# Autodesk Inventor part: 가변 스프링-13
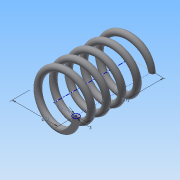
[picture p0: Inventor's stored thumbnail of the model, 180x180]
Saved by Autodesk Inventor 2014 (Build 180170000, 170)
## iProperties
Created: 2015-09
Part Number: 가변 스프링-13
Material: 강철, 탄소
Document SubType Name: Modeling
Designer: study
Density: 1 g/cm^3
Appearance: 반연마
Mass: 2.40348 g
Surface Area: 32.5802 cm^2
Volume: 2.40348 cm^3
Author: study
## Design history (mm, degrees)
sketch "스케치1"
  geometry: L1 (0, 0)-(11, 0); L2 (11, 0)-(11, 25.358); L3 (11, 25.358)-(0, 25.358); L4 (0, 25.358)-(0, 0); C1 r 1.5 at (11, 0)
  constraints: 8 end point, 2 parallel, 1 centre point, 1 coincident, 1 horizontal, 1 perpendicular
  dimensions: "d0" = 25.35829 distance of L1.end L2.end (derived); "d1" = 22 diameter of L1.end L4; "d2" = 3 diameter of C1
feature "코일1" sketch "스케치1" pitch "d3" = 10; turns "d5" = 5; dims "d4" = 25.35829 (= d0), "d6" = 0, angle "d7" = 90 deg, angle "d8" = 90 deg, "d9" = 0, "d10" = 0
node "작업 평면1"
sketch "스케치2"
  geometry: L1 (-12.5, 0)-(-9.5, 0) reference; 1 further point
  constraints: 1 horizontal alignment
extrude "돌출1" cut sketch "스케치2" stored distance "d12" = 10; taper "d13" = 0 deg
node "작업 평면2"
sketch "스케치3"
  geometry: L1 (-9.5, 0)-(-12.5, 0) reference; 1 further point
  constraints: 1 horizontal alignment
extrude "돌출2" cut sketch "스케치3" stored distance "d15" = 10; taper "d16" = 0 deg
node "솔리드1"
node "절단 모서리 투영1"
node "절단 모서리 투영2"
other parameters: "d11" = 0, "d14" = 25.35829 (= d0)
